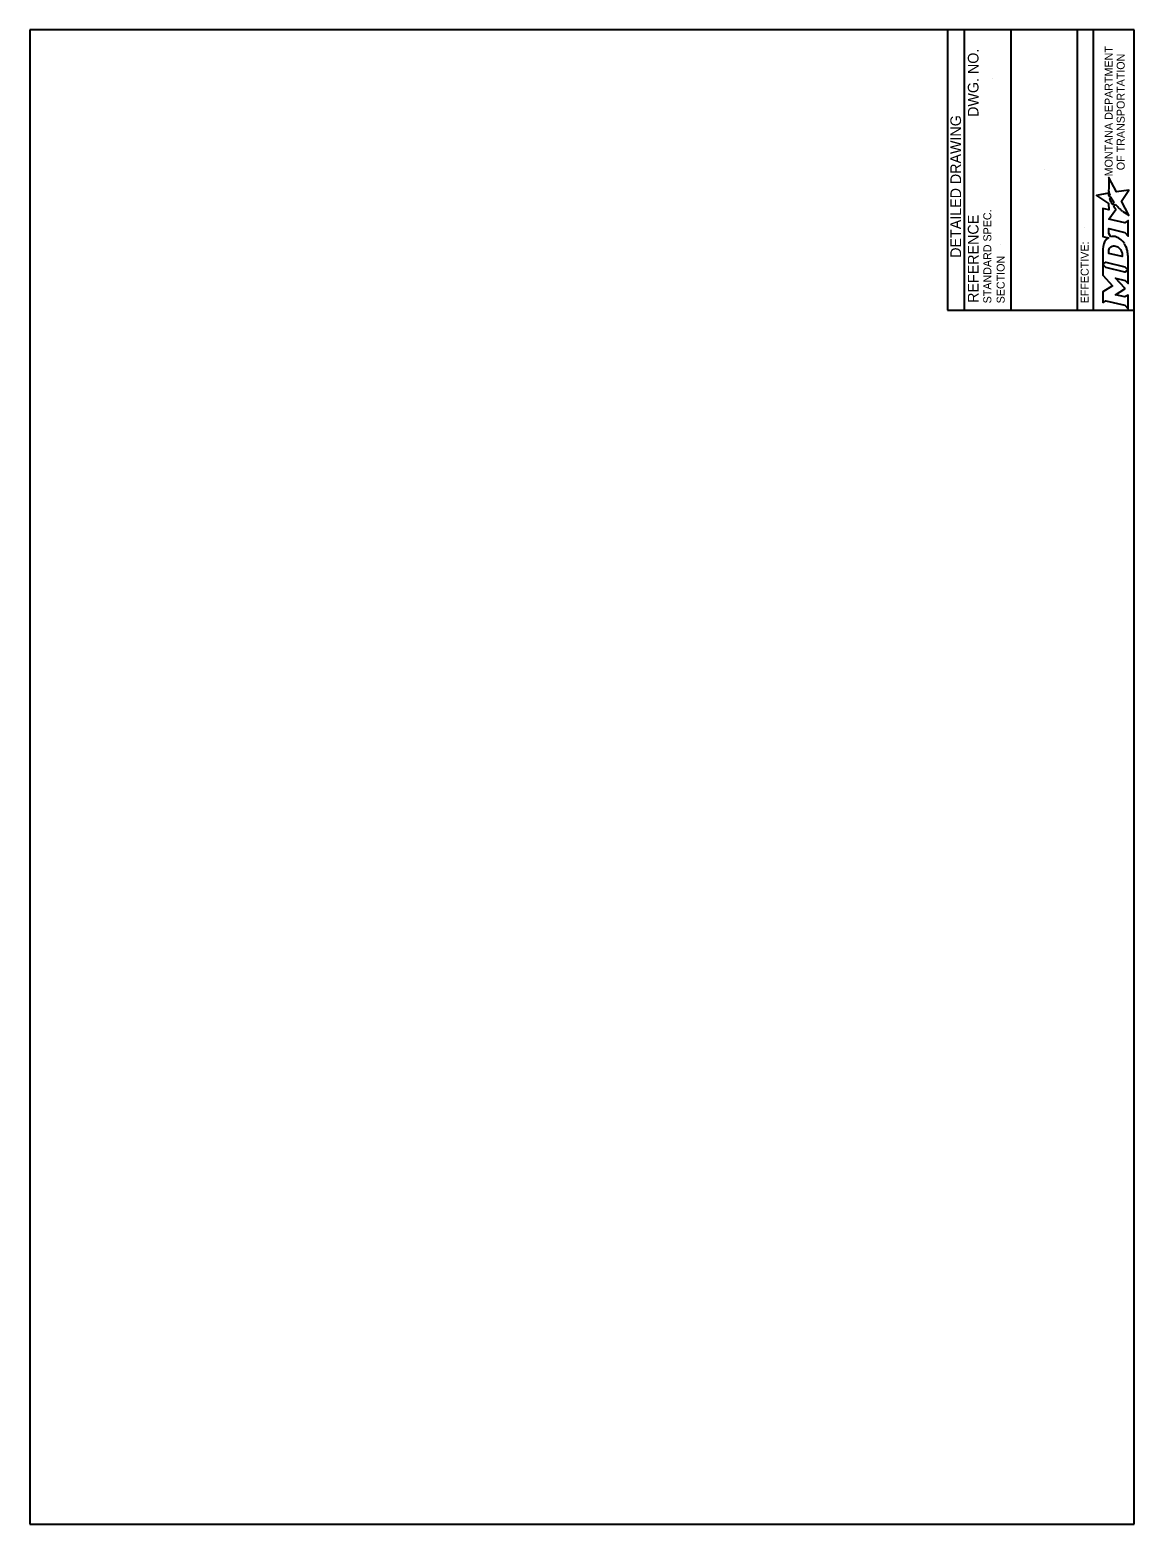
# Model space of a CAD drawing. Extents: x 49987.9 to 50021, y 49987.6 to 50011.4.
# Drawn here: x 49987.92 to 49996.19, y 49999.08 to 50010.28 of the extents above; entities that cross this region are included whole.
import ezdxf

# ---------------------------------------------------------------- set-up
doc = ezdxf.new("R2010")
doc.units = 0
for name, color, linetype in [('Default', 7, 'Continuous'), ('Level 1', 7, 'Continuous'), ('Level 4', 7, 'Continuous')]:
    doc.layers.add(name, color=color, linetype=linetype)

msp = doc.modelspace()

# ---------------------------------------------------------------- linework, layer by layer
at = {"layer": 'Default'}
for points in [[(49996.109, 50008.914), (49996.134, 50008.899), (49996.141, 50008.894), (49996.15, 50008.888), (49996.154, 50008.886), (49996.101, 50008.991), (49996.156, 50009.075), (49996.063, 50009.062), (49996.005, 50009.169), (49996.004, 50009.12), (49996.004, 50009.09), (49996.003, 50009.069), (49996.005, 50009.062), (49996.006, 50009.057), (49996.008, 50009.049), (49996.012, 50009.038)], [(49996.012, 50009.038), (49996.007, 50009.028), (49996.004, 50009.04), (49996.002, 50009.051), (49995.912, 50009.034), (49996.003, 50008.974), (49996.004, 50008.927), (49995.96, 50008.938), (49995.96, 50008.728), (49996.002, 50008.718), (49995.994, 50008.712)], [(49996.04, 50008.988), (49996.042, 50008.986), (49996.032, 50008.967), (49996.026, 50008.978), (49996.024, 50008.982), (49996.02, 50008.99), (49996.018, 50008.996), (49996.015, 50009.004), (49996.012, 50009.011), (49996.019, 50009.023), (49996.021, 50009.019), (49996.024, 50009.015), (49996.026, 50009.01), (49996.029, 50009.005), (49996.03, 50009.003), (49996.032, 50009.001), (49996.033, 50008.998), (49996.035, 50008.996), (49996.036, 50008.993), (49996.038, 50008.991), (49996.04, 50008.988)], [(49996.019, 50008.725), (49996.006, 50008.75), (49996.006, 50008.787), (49996.126, 50008.758), (49996.149, 50008.73), (49996.149, 50008.847), (49996.126, 50008.83), (49996.006, 50008.858), (49996.057, 50008.929), (49996.042, 50008.95), (49996.053, 50008.97)], [(49996.093, 50008.928), (49996.093, 50008.928)], [(49996.141, 50008.632), (49996.139, 50008.64), (49996.133, 50008.653), (49996.122, 50008.673)], [(49995.96, 50008.634), (49995.96, 50008.52), (49995.983, 50008.535), (49996.126, 50008.501), (49996.149, 50008.475), (49996.149, 50008.586)], [(49996.046, 50008.658), (49996.054, 50008.656), (49996.064, 50008.653), (49996.072, 50008.649), (49996.079, 50008.643), (49996.086, 50008.637), (49996.093, 50008.629), (49996.097, 50008.621), (49996.101, 50008.612), (49996.104, 50008.602), (49996.104, 50008.593), (49996.104, 50008.577), (49996.004, 50008.601), (49996.004, 50008.617), (49996.005, 50008.625), (49996.007, 50008.632), (49996.01, 50008.639), (49996.014, 50008.645), (49996.019, 50008.65), (49996.025, 50008.653), (49996.031, 50008.656), (49996.039, 50008.658), (49996.042, 50008.658), (49996.046, 50008.658)], [(49995.983, 50008.495), (49995.96, 50008.52), (49995.96, 50008.438), (49996.033, 50008.358), (49995.96, 50008.313), (49995.96, 50008.231)], [(49995.96, 50008.231), (49995.983, 50008.246), (49996.126, 50008.212), (49996.149, 50008.186), (49996.149, 50008.288), (49996.126, 50008.274), (49996.056, 50008.291), (49996.125, 50008.334), (49996.125, 50008.34), (49996.055, 50008.415), (49996.127, 50008.398), (49996.149, 50008.374), (49996.149, 50008.475), (49996.125, 50008.461), (49995.983, 50008.495)]]:
    msp.add_lwpolyline(points, dxfattribs=at)
for centre, radius, start, end in [((49996.038, 50008.657), 0.0709, 69.5329, 105.8582), ((49996.021, 50008.613), 0.118, 30.9103, 69.1383)]:
    msp.add_arc(centre, radius, start, end, dxfattribs=at)
for centre, major_axis, ratio, start_param, end_param in [((49996.063, 50008.959), (0.0097, -0.0112), 0.021651, 3.157348, 6.283185), ((49996.083, 50008.938), (0.0102, -0.0098), 0.016458, 3.141593, 6.279097), ((49996.101, 50008.921), (0.00806, -0.00694), 0.008222, 0, 3.137361), ((49996.007, 50008.631), (0.0037, 0.0834), 0.568097, 0.61298, 1.570796), ((49996, 50008.687), (0.0295, 0.0361), 0.469099, 1.225588, 1.570796), ((49996, 50008.586), (-0.148, 0), 0.987302, 3.139398, 3.456847)]:
    msp.add_ellipse(centre, major_axis=major_axis, ratio=ratio, start_param=start_param, end_param=end_param, dxfattribs=at)
at = {"layer": 'Level 1'}
for points in [[(49987.916, 50010.276), (49987.916, 49999.076)], [(49996.195, 50010.276), (49987.916, 50010.276)], [(49996.195, 49999.076), (49996.195, 50010.276)], [(49987.916, 49999.076), (49996.195, 49999.076)]]:
    msp.add_lwpolyline(points, dxfattribs=at)
at = {"layer": 'Level 4'}
for p, q in [((49994.795, 50010.276), (49994.795, 50008.176)), ((49994.92, 50010.276), (49994.92, 50008.176)), ((49995.27, 50010.276), (49995.27, 50008.176)), ((49995.768, 50010.276), (49995.768, 50008.176)), ((49995.888, 50010.276), (49995.888, 50008.176)), ((49995.135, 50009.912), (49995.135, 50009.912)), ((49995.519, 50009.226), (49995.519, 50009.226)), ((49995.824, 50008.791), (49995.824, 50008.791)), ((49995.194, 50008.67), (49995.194, 50008.67)), ((49994.795, 50008.176), (49996.195, 50008.176))]:
    msp.add_line(p, q, dxfattribs=at)

# ---------------------------------------------------------------- texts
at = {"layer": 'Default'}
for s, p in [('MONTANA DEPARTMENT', (49996.034, 50009.178)), ('OF TRANSPORTATION', (49996.124, 50009.224))]:
    msp.add_text(s, height=0.06, rotation=90, dxfattribs=at).set_placement(p)
at = {"layer": 'Level 4'}
for s, height, p in [('DWG. NO.', 0.08, (49995.028, 50009.624)), ('DETAILED DRAWING', 0.0799, (49994.897, 50008.568)), ('STANDARD SPEC.', 0.06, (49995.124, 50008.226)), ('REFERENCE', 0.08, (49995.028, 50008.23)), ('EFFECTIVE:', 0.06, (49995.854, 50008.226)), ('SECTION', 0.06, (49995.224, 50008.226))]:
    msp.add_text(s, height=height, rotation=90, dxfattribs=at).set_placement(p)

doc.saveas('drawing.dxf')
